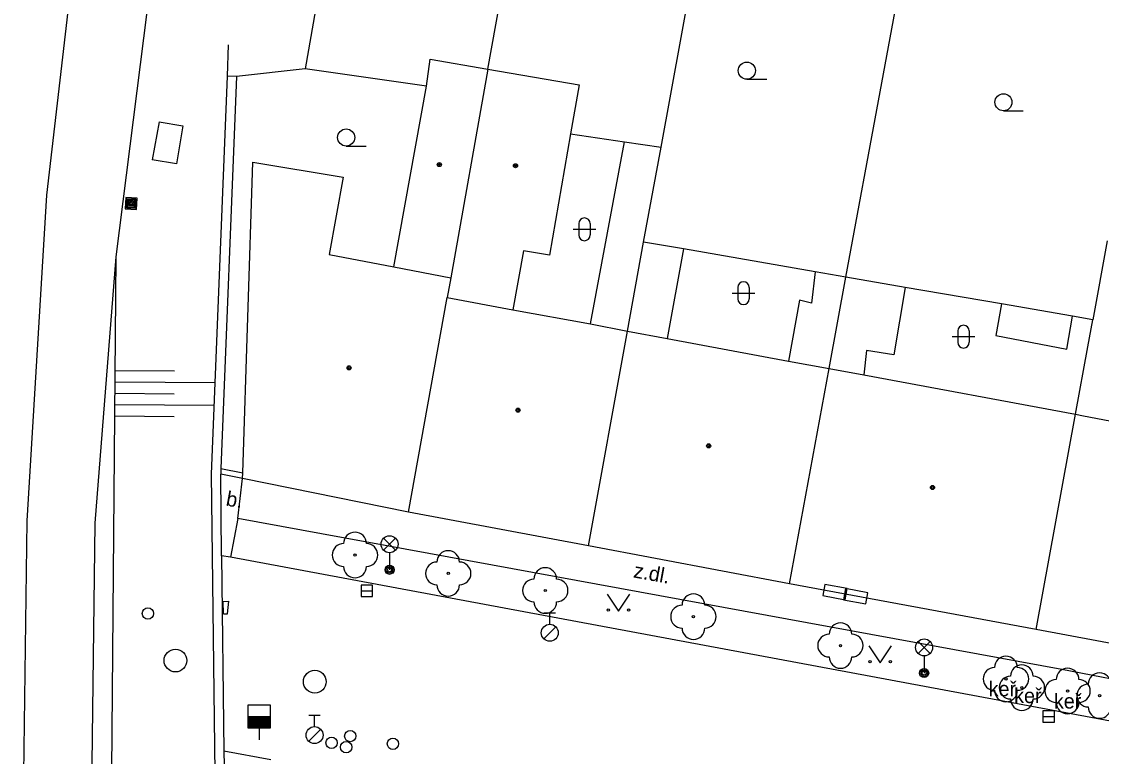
# Model space of a CAD drawing. Extents: x -596229 to -595156, y -1161237 to -1159376.
# Drawn here: x -596138.97 to -596091.46, y -1160406.71 to -1160374.4 of the extents above; entities that cross this region are included whole.
import ezdxf

# ---------------------------------------------------------------- set-up
doc = ezdxf.new("R2010")
doc.units = 0
for name, color, linetype in [('DOP - kresba z DSPS bez souradnic', 7, 'Continuous'), ('DOP - rozhrani ploch obecne', 7, 'Continuous'), ('Level 22', 7, 'Continuous'), ('Level 24', 7, 'Continuous'), ('Level 25', 7, 'Continuous'), ('Level 27', 7, 'Continuous'), ('Level 28', 7, 'Continuous'), ('Level 33', 7, 'Continuous'), ('Level 36', 7, 'Continuous'), ('Level 39', 7, 'Continuous'), ('plynovod - povrch.  znaky - PRIS skut. velikost', 7, 'Continuous'), ('TM - budovy zdene_ betonove - VP', 7, 'Continuous'), ('TM - CD - osa koleji', 7, 'Continuous'), ('TM - chodniky - VP', 7, 'Continuous'), ('TM - horni hrana svahu', 7, 'Continuous'), ('TM - komunikace - VP', 7, 'Continuous'), ('TM - letecke snimky - pomocna linie', 7, 'Continuous'), ('TM - plot nerozliseny - VP', 7, 'Continuous'), ('TM - popis povrchu', 7, 'Continuous'), ('TM - popis zelene', 7, 'Continuous'), ('TM - rozhrani ploch obecne - VP', 7, 'Continuous'), ('TM - srafovani', 7, 'Continuous'), ('TM - zed operna - VP', 7, 'Continuous')]:
    doc.layers.add(name, color=color, linetype=linetype)

msp = doc.modelspace()

# ---------------------------------------------------------------- linework, layer by layer
at = {"layer": 'DOP - kresba z DSPS bez souradnic'}
for points in [[(-596113.94, -1160387.7), (-596112.44, -1160379.69)], [(-596109.85, -1160384.4), (-596110.57, -1160388.34)], [(-596104.06, -1160385.4), (-596104.22, -1160386.78)], [(-596100.09, -1160386.09), (-596100.59, -1160389.06)], [(-596104.75, -1160386.65), (-596105.23, -1160389.33)], [(-596104.22, -1160386.78), (-596104.75, -1160386.65)], [(-596095.86, -1160386.82), (-596096.1, -1160388.21)], [(-596092.98, -1160388.81), (-596092.73, -1160387.36)], [(-596096.1, -1160388.21), (-596092.98, -1160388.81)], [(-596101.8, -1160388.86), (-596101.92, -1160389.93)], [(-596100.59, -1160389.06), (-596101.8, -1160388.86)]]:
    msp.add_lwpolyline(points, dxfattribs=at)
at = {"layer": 'DOP - rozhrani ploch obecne'}
for points in [[(-596118.45, -1160376.49), (-596116.58, -1160366.08)], [(-596110.83, -1160379.93), (-596108.59, -1160367.61)], [(-596102.7, -1160385.64), (-596099.68, -1160369.32)], [(-596114.82, -1160379.34), (-596112.44, -1160379.69)], [(-596112.44, -1160379.69), (-596110.83, -1160379.93)], [(-596111.6, -1160384.1), (-596110.83, -1160379.93)], [(-596112.31, -1160388.01), (-596111.6, -1160384.1)], [(-596109.85, -1160384.4), (-596111.6, -1160384.1)], [(-596091.21, -1160384.05), (-596091.84, -1160387.51)], [(-596104.06, -1160385.4), (-596109.85, -1160384.4)], [(-596102.7, -1160385.64), (-596104.06, -1160385.4)], [(-596103.44, -1160389.66), (-596102.7, -1160385.64)], [(-596100.09, -1160386.09), (-596102.7, -1160385.64)], [(-596095.86, -1160386.82), (-596100.09, -1160386.09)], [(-596092.73, -1160387.36), (-596095.86, -1160386.82)], [(-596091.84, -1160387.51), (-596092.73, -1160387.36)], [(-596092.06, -1160388.71), (-596091.84, -1160387.51)], [(-596092.6, -1160391.67), (-596092.06, -1160388.71)]]:
    msp.add_lwpolyline(points, dxfattribs=at)
at = {"layer": 'Level 22'}
for centre in [(-596124.3, -1160397.86), (-596120.2, -1160398.67), (-596115.93, -1160399.42), (-596109.41, -1160400.57), (-596102.94, -1160401.84), (-596095.66, -1160403.31), (-596094.96, -1160403.69), (-596092.95, -1160403.84), (-596091.54, -1160404.04)]:
    msp.add_circle(centre, 0.05, dxfattribs=at)
for centre, start, end in [((-596124.3, -1160397.36), 0, 180), ((-596124.8, -1160397.86), 90, 270), ((-596123.8, -1160397.86), 270, 90), ((-596120.2, -1160398.17), 0, 180), ((-596124.3, -1160398.36), 180, 0), ((-596120.7, -1160398.67), 90, 270), ((-596119.7, -1160398.67), 270, 90), ((-596115.93, -1160398.92), 0, 180), ((-596120.2, -1160399.17), 180, 0), ((-596116.43, -1160399.42), 90, 270), ((-596115.43, -1160399.42), 270, 90), ((-596109.41, -1160400.07), 0, 180), ((-596115.93, -1160399.92), 180, 0), ((-596109.91, -1160400.57), 90, 270), ((-596108.91, -1160400.57), 270, 90), ((-596109.41, -1160401.07), 180, 0), ((-596102.94, -1160401.34), 0, 180), ((-596103.44, -1160401.84), 90, 270), ((-596102.44, -1160401.84), 270, 90), ((-596102.94, -1160402.34), 180, 0), ((-596095.66, -1160402.81), 0, 180), ((-596094.96, -1160403.19), 0, 180), ((-596096.16, -1160403.31), 90, 270), ((-596095.16, -1160403.31), 270, 90), ((-596092.95, -1160403.34), 0, 180), ((-596091.54, -1160403.54), 0, 180), ((-596095.46, -1160403.69), 90, 270), ((-596094.46, -1160403.69), 270, 90), ((-596093.45, -1160403.84), 90, 270), ((-596092.04, -1160404.04), 90, 270), ((-596092.45, -1160403.84), 270, 90), ((-596095.66, -1160403.81), 180, 0), ((-596094.96, -1160404.19), 180, 0), ((-596092.95, -1160404.34), 180, 0), ((-596091.54, -1160404.54), 180, 0)]:
    msp.add_arc(centre, 0.5, start, end, dxfattribs=at)
at = {"layer": 'Level 24'}
for points in [[(-596103.724, -1160399.645), (-596102.741, -1160399.827), (-596102.65, -1160399.336), (-596103.633, -1160399.154)], [(-596102.805, -1160399.826), (-596101.822, -1160400.008), (-596101.731, -1160399.517), (-596102.714, -1160399.335)]]:
    msp.add_lwpolyline(points, close=True, dxfattribs=at)
at = {"layer": 'Level 25'}
for points in [[(-596134.41, -1160382.64), (-596133.91, -1160382.66), (-596133.89, -1160382.16), (-596134.39, -1160382.14)], [(-596134.358, -1160382.592), (-596133.958, -1160382.608), (-596133.942, -1160382.208), (-596134.342, -1160382.192)], [(-596134.306, -1160382.544), (-596134.006, -1160382.556), (-596133.994, -1160382.256), (-596134.294, -1160382.244)], [(-596134.254, -1160382.496), (-596134.054, -1160382.504), (-596134.046, -1160382.304), (-596134.246, -1160382.296)], [(-596134.202, -1160382.448), (-596134.102, -1160382.452), (-596134.098, -1160382.352), (-596134.198, -1160382.348)]]:
    msp.add_lwpolyline(points, close=True, dxfattribs=at)
at = {"layer": 'Level 27'}
for p, q in [((-596124.03, -1160399.44), (-596123.53, -1160399.44)), ((-596094.03, -1160404.96), (-596093.53, -1160404.96))]:
    msp.add_line(p, q, dxfattribs=at)
for points in [[(-596124.03, -1160399.69), (-596123.53, -1160399.69), (-596123.53, -1160399.19), (-596124.03, -1160399.19)], [(-596094.03, -1160405.21), (-596093.53, -1160405.21), (-596093.53, -1160404.71), (-596094.03, -1160404.71)]]:
    msp.add_lwpolyline(points, close=True, dxfattribs=at)
for centre in [(-596132.2, -1160402.5), (-596126.07, -1160403.43)]:
    msp.add_circle(centre, 0.5, dxfattribs=at)
at = {"layer": 'Level 28'}
for p, q in [((-596115.98, -1160400.405), (-596115.48, -1160400.405)), ((-596115.73, -1160400.905), (-596115.73, -1160400.405)), ((-596115.988, -1160401.552), (-596115.458, -1160401.022)), ((-596129.02, -1160404.96), (-596128.02, -1160404.96)), ((-596129.02, -1160405.01), (-596128.02, -1160405.01)), ((-596129.02, -1160405.06), (-596128.02, -1160405.06)), ((-596126.33, -1160404.905), (-596125.83, -1160404.905)), ((-596126.08, -1160405.405), (-596126.08, -1160404.905)), ((-596129.02, -1160405.11), (-596128.02, -1160405.11)), ((-596129.02, -1160405.16), (-596128.02, -1160405.16)), ((-596129.02, -1160405.21), (-596128.02, -1160405.21)), ((-596129.02, -1160405.26), (-596128.02, -1160405.26)), ((-596129.02, -1160405.31), (-596128.02, -1160405.31)), ((-596129.02, -1160405.36), (-596128.02, -1160405.36)), ((-596129.02, -1160405.41), (-596128.02, -1160405.41)), ((-596128.52, -1160405.46), (-596128.52, -1160405.99)), ((-596126.338, -1160406.052), (-596125.808, -1160405.522))]:
    msp.add_line(p, q, dxfattribs=at)
msp.add_lwpolyline([(-596129.02, -1160405.46), (-596128.02, -1160405.46), (-596128.02, -1160404.46), (-596129.02, -1160404.46)], close=True, dxfattribs=at)
for centre, radius in [((-596133.41, -1160400.43), 0.25), ((-596115.73, -1160401.28), 0.375), ((-596126.08, -1160405.78), 0.375), ((-596125.33, -1160406.12), 0.25), ((-596124.51, -1160405.82), 0.25), ((-596122.63, -1160406.16), 0.25), ((-596124.69, -1160406.31), 0.25)]:
    msp.add_circle(centre, radius, dxfattribs=at)
at = {"layer": 'Level 33'}
for p, q in [((-596123.045, -1160397.65), (-596122.515, -1160397.12)), ((-596123.045, -1160397.12), (-596122.515, -1160397.65)), ((-596122.78, -1160397.76), (-596122.78, -1160398.51)), ((-596099.525, -1160402.19), (-596098.995, -1160401.66)), ((-596099.525, -1160401.66), (-596098.995, -1160402.19)), ((-596099.26, -1160402.3), (-596099.26, -1160403.05))]:
    msp.add_line(p, q, dxfattribs=at)
for centre, radius in [((-596122.78, -1160397.385), 0.375), ((-596122.78, -1160398.51), 0.2), ((-596122.78, -1160398.51), 0.145), ((-596122.78, -1160398.51), 0.0876), ((-596099.26, -1160401.925), 0.375), ((-596099.26, -1160403.05), 0.2), ((-596099.26, -1160403.05), 0.145), ((-596099.26, -1160403.05), 0.0876)]:
    msp.add_circle(centre, radius, dxfattribs=at)
at = {"layer": 'Level 36'}
for p, q in [((-596107.06, -1160376.935), (-596106.185, -1160376.935)), ((-596095.77, -1160378.325), (-596094.895, -1160378.325)), ((-596124.69, -1160379.875), (-596123.815, -1160379.875)), ((-596114.706, -1160383.536), (-596113.706, -1160383.536)), ((-596114.456, -1160383.286), (-596114.456, -1160383.786)), ((-596113.956, -1160383.286), (-596113.956, -1160383.786)), ((-596107.706, -1160386.346), (-596106.706, -1160386.346)), ((-596107.456, -1160386.096), (-596107.456, -1160386.596)), ((-596106.956, -1160386.096), (-596106.956, -1160386.596)), ((-596098.026, -1160388.256), (-596097.026, -1160388.256)), ((-596097.776, -1160388.006), (-596097.776, -1160388.506)), ((-596097.276, -1160388.006), (-596097.276, -1160388.506))]:
    msp.add_line(p, q, dxfattribs=at)
for points in [[(-596113.21, -1160399.58), (-596112.71, -1160400.33), (-596112.21, -1160399.58)], [(-596101.69, -1160401.85), (-596101.19, -1160402.6), (-596100.69, -1160401.85)]]:
    msp.add_lwpolyline(points, dxfattribs=at)
for centre, radius in [((-596107.06, -1160376.56), 0.375), ((-596095.77, -1160377.95), 0.375), ((-596124.69, -1160379.5), 0.375), ((-596113.16, -1160400.28), 0.05), ((-596112.261, -1160400.28), 0.05), ((-596101.64, -1160402.55), 0.05), ((-596100.741, -1160402.55), 0.05)]:
    msp.add_circle(centre, radius, dxfattribs=at)
for centre, start, end in [((-596114.206, -1160383.286), 0, 180), ((-596114.206, -1160383.786), 180, 0), ((-596107.206, -1160386.096), 0, 180), ((-596107.206, -1160386.596), 180, 0), ((-596097.526, -1160388.006), 0, 180), ((-596097.526, -1160388.506), 180, 0)]:
    msp.add_arc(centre, 0.25, start, end, dxfattribs=at)
at = {"layer": 'Level 39'}
for centre, radius in [((-596120.59, -1160380.69), 0.09), ((-596120.59, -1160380.69), 0.0398), ((-596117.24, -1160380.74), 0.09), ((-596117.24, -1160380.74), 0.0398), ((-596124.56, -1160389.63), 0.09), ((-596124.56, -1160389.63), 0.0398), ((-596117.13, -1160391.49), 0.09), ((-596117.13, -1160391.49), 0.0398), ((-596108.74, -1160393.06), 0.09), ((-596108.74, -1160393.06), 0.0398), ((-596098.89, -1160394.89), 0.09), ((-596098.89, -1160394.89), 0.0398)]:
    msp.add_circle(centre, radius, dxfattribs=at)
at = {"layer": 'plynovod - povrch.  znaky - PRIS skut. velikost'}
for points in [[(-596130.09, -1160400.44), (-596130.1, -1160399.9), (-596129.85, -1160399.89)], [(-596129.91, -1160400.44), (-596129.85, -1160399.89)], [(-596130.09, -1160400.44), (-596129.91, -1160400.44)]]:
    msp.add_lwpolyline(points, dxfattribs=at)
at = {"layer": 'TM - budovy zdene_ betonove - VP'}
for points in [[(-596121.15, -1160377.24), (-596120.99, -1160376.05)], [(-596120.99, -1160376.05), (-596118.45, -1160376.49)], [(-596118.45, -1160376.49), (-596120.09, -1160385.67)], [(-596118.45, -1160376.49), (-596114.44, -1160377.19)], [(-596122.59, -1160385.19), (-596121.15, -1160377.24)], [(-596114.44, -1160377.19), (-596114.82, -1160379.34)], [(-596114.82, -1160379.34), (-596115.75, -1160384.68)], [(-596129.24, -1160394.24), (-596128.8, -1160380.59)], [(-596128.8, -1160380.59), (-596124.82, -1160381.24)], [(-596124.82, -1160381.24), (-596125.43, -1160384.65)], [(-596116.88, -1160384.48), (-596117.35, -1160387.08)], [(-596115.75, -1160384.68), (-596116.88, -1160384.48)], [(-596125.43, -1160384.65), (-596122.59, -1160385.19)], [(-596122.59, -1160385.19), (-596120.09, -1160385.67)], [(-596120.09, -1160385.67), (-596120.25, -1160386.54)], [(-596121.95, -1160395.97), (-596120.25, -1160386.54)], [(-596120.25, -1160386.54), (-596117.35, -1160387.08)], [(-596117.35, -1160387.08), (-596113.94, -1160387.7)], [(-596113.94, -1160387.7), (-596112.31, -1160388.01)], [(-596114.03, -1160397.45), (-596112.31, -1160388.01)], [(-596112.31, -1160388.01), (-596110.57, -1160388.34)], [(-596110.57, -1160388.34), (-596105.23, -1160389.33)], [(-596105.23, -1160389.33), (-596103.44, -1160389.66)], [(-596105.19, -1160399.12), (-596103.44, -1160389.66)], [(-596103.44, -1160389.66), (-596101.92, -1160389.93)], [(-596101.92, -1160389.93), (-596092.6, -1160391.67)], [(-596094.33, -1160401.13), (-596092.6, -1160391.67)], [(-596092.6, -1160391.67), (-596092.25, -1160391.74)], [(-596092.25, -1160391.74), (-596089.01, -1160392.35)], [(-596129.25, -1160394.5), (-596129.24, -1160394.24)], [(-596121.95, -1160395.97), (-596129.25, -1160394.5)], [(-596114.03, -1160397.45), (-596121.95, -1160395.97)], [(-596105.19, -1160399.12), (-596114.03, -1160397.45)], [(-596094.33, -1160401.13), (-596105.19, -1160399.12)], [(-596087.42, -1160402.43), (-596094.33, -1160401.13)]]:
    msp.add_lwpolyline(points, dxfattribs=at)
at = {"layer": 'TM - CD - osa koleji'}
msp.add_lwpolyline([(-596070.84, -1160662.58), (-596079.19, -1160639.25), (-596089.53, -1160610.33), (-596100.36, -1160580), (-596108.92, -1160555.81), (-596119.29, -1160525.88), (-596123.37, -1160513.21), (-596128.62, -1160494.53), (-596133.1, -1160473.96), (-596137.29, -1160444.66), (-596137.85, -1160438.46), (-596138.97, -1160415.3), (-596138.73, -1160396.35), (-596137.86, -1160382.04), (-596135.04, -1160357.75), (-596130.33, -1160332.57), (-596130.02, -1160331.12), (-596125.76, -1160311.5)], dxfattribs=at)
at = {"layer": 'TM - chodniky - VP'}
for points in [[(-596129.46, -1160396.25), (-596129.25, -1160394.5)], [(-596087.75, -1160403.91), (-596089.25, -1160403.65), (-596093.2, -1160402.9), (-596129.46, -1160396.25)]]:
    msp.add_lwpolyline(points, dxfattribs=at)
at = {"layer": 'TM - horni hrana svahu'}
for points in [[(-596134.81, -1160384.75), (-596131.29, -1160356.93), (-596128.77, -1160341.13)], [(-596068.78, -1160660.14), (-596070.7, -1160650.38), (-596075.5, -1160636.41), (-596084.94, -1160608.71), (-596096.48, -1160580.01), (-596099.31, -1160572.83), (-596115.34, -1160526.77), (-596124.43, -1160494.43), (-596128.99, -1160469.32), (-596133.17, -1160440.33), (-596135.09, -1160417.8), (-596134.81, -1160384.75)]]:
    msp.add_lwpolyline(points, dxfattribs=at)
at = {"layer": 'TM - komunikace - VP'}
for points in [[(-596130.17, -1160397.89), (-596130.07, -1160406.49)], [(-596129.78, -1160397.96), (-596130.17, -1160397.89)], [(-596088.09, -1160405.68), (-596089.56, -1160405.44), (-596129.78, -1160397.96)], [(-596128, -1160406.87), (-596130.07, -1160406.49)]]:
    msp.add_lwpolyline(points, dxfattribs=at)
at = {"layer": 'TM - letecke snimky - pomocna linie'}
for points in [[(-596129.52, -1160376.82), (-596129.91, -1160376.8)], [(-596115.45, -1160527.8), (-596116.44, -1160524.93), (-596120.5, -1160512.34), (-596125.71, -1160493.8), (-596129.06, -1160478.39), (-596129.71, -1160475.42), (-596130.15, -1160473.43), (-596134.31, -1160444.31), (-596134.86, -1160438.25), (-596135.58, -1160423.21), (-596135.62, -1160422.49), (-596135.97, -1160415.25), (-596135.73, -1160396.46), (-596134.81, -1160384.75)]]:
    msp.add_lwpolyline(points, dxfattribs=at)
at = {"layer": 'TM - plot nerozliseny - VP'}
for points in [[(-596124.41, -1160364.58), (-596126.49, -1160376.48)], [(-596126.49, -1160376.48), (-596129.52, -1160376.82)]]:
    msp.add_lwpolyline(points, dxfattribs=at)
at = {"layer": 'TM - rozhrani ploch obecne - VP'}
for points in [[(-596121.15, -1160377.24), (-596126.49, -1160376.48)], [(-596129.52, -1160376.82), (-596130.2, -1160394.05)], [(-596132.92, -1160378.81), (-596131.87, -1160378.98), (-596132.15, -1160380.66), (-596133.22, -1160380.48)], [(-596132.92, -1160378.81), (-596133.22, -1160380.48)], [(-596130.2, -1160394.05), (-596130.21, -1160394.31)], [(-596130.2, -1160394.05), (-596129.24, -1160394.24)], [(-596129.25, -1160394.5), (-596130.21, -1160394.31)], [(-596130.17, -1160397.89), (-596130.21, -1160394.31)], [(-596129.46, -1160396.25), (-596129.78, -1160397.96)], [(-596130.07, -1160406.49), (-596130.03, -1160408.35)]]:
    msp.add_lwpolyline(points, dxfattribs=at)
at = {"layer": 'TM - srafovani'}
for points in [[(-596132.24, -1160389.78), (-596134.85, -1160389.76)], [(-596130.45, -1160390.29), (-596134.86, -1160390.26)], [(-596132.25, -1160390.78), (-596134.86, -1160390.76)], [(-596130.49, -1160391.29), (-596134.87, -1160391.26)], [(-596132.26, -1160391.78), (-596134.87, -1160391.76)]]:
    msp.add_lwpolyline(points, dxfattribs=at)
at = {"layer": 'TM - zed operna - VP'}
for points in [[(-596129.91, -1160376.8), (-596129.86, -1160375.43)], [(-596130.61, -1160394.31), (-596129.91, -1160376.8)], [(-596130.43, -1160409.85), (-596130.61, -1160394.31)]]:
    msp.add_lwpolyline(points, dxfattribs=at)

# ---------------------------------------------------------------- texts
at = {"layer": 'TM - popis povrchu'}
for s, rotation, p in [('b.', 349.5846, (-596130.01, -1160395.68)), ('z.dl.', 349.6861, (-596112.08, -1160398.84))]:
    msp.add_text(s, height=0.65, rotation=rotation, dxfattribs=at).set_placement(p)
at = {"layer": 'TM - popis zelene'}
for p in [(-596096.42, -1160404.07), (-596095.3, -1160404.37), (-596093.55, -1160404.61)]:
    msp.add_text('keř', height=0.65, dxfattribs=at).set_placement(p)

doc.saveas('drawing.dxf')
